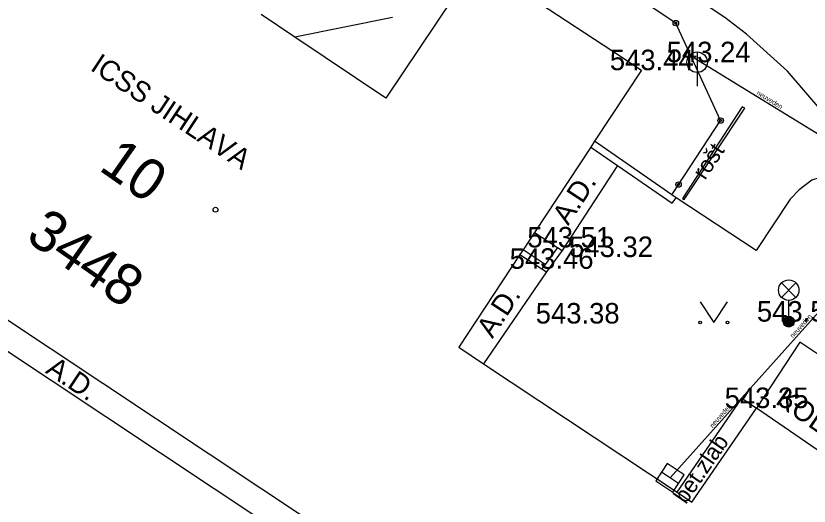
# Model space of a CAD drawing. Extents: x -669393 to -668650, y -1126925 to -1126294.
# Drawn here: x -668905.4 to -668876.38, y -1126626.61 to -1126608.7 of the extents above; entities that cross this region are included whole.
import ezdxf

# ---------------------------------------------------------------- set-up
doc = ezdxf.new("R2010")
doc.units = 0
for name, color, linetype in [('G_Bod_tecka', 7, 'Continuous'), ('G_Bod_vyska', 7, 'Continuous'), ('G_Budovy-znacky', 7, 'Continuous'), ('G_Budovy_Objekty', 7, 'Continuous'), ('G_Budovy_vstupy', 7, 'Continuous'), ('G_Cesty_Schody', 7, 'Continuous'), ('G_Cisla_orientacni', 7, 'Continuous'), ('G_Cisla_popisna', 7, 'Continuous'), ('G_Objekty_technicke', 7, 'Continuous'), ('G_Plochy_zpevnene', 7, 'Continuous'), ('G_Ploty', 7, 'Continuous'), ('G_Popisy_objektu', 7, 'Continuous'), ('G_Popisy_povrchu', 7, 'Continuous'), ('G_Poznamky_odkaz', 7, 'Continuous'), ('G_Site-kanalizace', 7, 'Continuous'), ('G_Site-Sloupy', 7, 'Continuous'), ('G_Z_KANAL_podz_kotovane', 7, 'Continuous'), ('G_Zelen-Znacky', 7, 'Continuous'), ('Vrstva 13', 7, 'Continuous'), ('Vrstva 3', 7, 'Continuous')]:
    doc.layers.add(name, color=color, linetype=linetype)

msp = doc.modelspace()

# ---------------------------------------------------------------- linework, layer by layer
at = {"layer": 'G_Bod_tecka'}
for p, q in [((-668880.43, -1126610.39), (-668880.43, -1126610.39)), ((-668882.51, -1126610.68), (-668882.51, -1126610.68)), ((-668885.59, -1126617.16), (-668885.59, -1126617.16)), ((-668884, -1126617.51), (-668884, -1126617.51)), ((-668886.16, -1126617.94), (-668886.16, -1126617.94)), ((-668885.22, -1126619.94), (-668885.22, -1126619.94)), ((-668877.13, -1126619.87), (-668877.13, -1126619.87)), ((-668878.31, -1126623.03), (-668878.31, -1126623.03))]:
    msp.add_line(p, q, dxfattribs=at)
at = {"layer": 'G_Budovy-znacky'}
msp.add_circle((-668898.099, -1126615.78), 0.0875, dxfattribs=at)
at = {"layer": 'G_Budovy_Objekty'}
for p, q in [((-668888.53, -1126606.7), (-668891.87, -1126611.7)), ((-668895.19, -1126609.47), (-668896.43, -1126608.64)), ((-668891.87, -1126611.7), (-668895.19, -1126609.47)), ((-668883.56, -1126609.99), (-668882.51, -1126610.68)), ((-668884.37, -1126613.49), (-668886.43, -1126616.61)), ((-668913.94, -1126614.34), (-668894.48, -1126627.26)), ((-668886.43, -1126616.61), (-668886.85, -1126617.25)), ((-668886.85, -1126617.25), (-668886.96, -1126617.42)), ((-668886.96, -1126617.42), (-668889.2, -1126620.81)), ((-668889.2, -1126620.81), (-668888.3, -1126621.41)), ((-668876.72, -1126620.62), (-668878.31, -1126623.03)), ((-668888.3, -1126621.41), (-668881.21, -1126626.11)), ((-668880.68, -1126626.47), (-668878.31, -1126623.03)), ((-668874.51, -1126625.65), (-668878.31, -1126623.03)), ((-668881.21, -1126626.11), (-668880.68, -1126626.47))]:
    msp.add_line(p, q, dxfattribs=at)
for points in [[(-668881.41, -1126615.23), (-668879.62, -1126612.52), (-668881.26, -1126608.96), (-668884.32, -1126606.92), (-668887.36, -1126604.92), (-668888.53, -1126606.7)], [(-668886.39, -1126608.12), (-668886.28, -1126608.2), (-668883.56, -1126609.99)], [(-668882.51, -1126610.68), (-668884.23, -1126613.28), (-668884.37, -1126613.49)]]:
    msp.add_lwpolyline(points, dxfattribs=at)
at = {"layer": 'G_Budovy_vstupy'}
msp.add_line((-668875.37, -1126621.53), (-668876.72, -1126620.62), dxfattribs=at)
at = {"layer": 'G_Cesty_Schody'}
for p, q in [((-668883.39, -1126614.16), (-668885.42, -1126617.27)), ((-668914.47, -1126615.14), (-668895, -1126628.05)), ((-668885.59, -1126617.16), (-668885.42, -1126617.27)), ((-668886.16, -1126617.94), (-668885.99, -1126618.05)), ((-668885.99, -1126618.05), (-668888.3, -1126621.41))]:
    msp.add_line(p, q, dxfattribs=at)
for points in [[(-668879.47, -1126608.75), (-668887.91, -1126603.16)], [(-668874.12, -1126614.81), (-668875.91, -1126612.19), (-668877.17, -1126610.71), (-668878.68, -1126609.36), (-668879.47, -1126608.75)], [(-668880.96, -1126615.41), (-668878.74, -1126612.07), (-668878.83, -1126612.02), (-668881.02, -1126615.37), (-668880.96, -1126615.41)]]:
    msp.add_lwpolyline(points, dxfattribs=at)
at = {"layer": 'G_Objekty_technicke'}
for p, q in [((-668877.395, -1126618.455), (-668876.865, -1126618.985)), ((-668877.395, -1126618.985), (-668876.865, -1126618.455)), ((-668877.13, -1126619.87), (-668877.13, -1126619.095))]:
    msp.add_line(p, q, dxfattribs=at)
for centre, radius in [((-668877.13, -1126618.72), 0.375), ((-668877.13, -1126619.87), 0.2), ((-668877.13, -1126619.87), 0.18), ((-668877.13, -1126619.87), 0.16), ((-668877.13, -1126619.87), 0.14), ((-668877.13, -1126619.87), 0.12), ((-668877.13, -1126619.87), 0.1), ((-668877.13, -1126619.87), 0.08), ((-668877.13, -1126619.87), 0.06), ((-668877.13, -1126619.87), 0.04), ((-668877.13, -1126619.87), 0.02)]:
    msp.add_circle(centre, radius, dxfattribs=at)
at = {"layer": 'G_Plochy_zpevnene'}
for p, q in [((-668891.62, -1126608.75), (-668895.19, -1126609.47)), ((-668881.21, -1126626.11), (-668878.84, -1126622.67)), ((-668878.84, -1126622.67), (-668878.31, -1126623.03))]:
    msp.add_line(p, q, dxfattribs=at)
for points in [[(-668881.39, -1126615.54), (-668881.25, -1126615.34), (-668881.41, -1126615.23), (-668884.23, -1126613.28)], [(-668884.37, -1126613.49), (-668883.39, -1126614.16), (-668881.39, -1126615.54)], [(-668874.12, -1126614.81), (-668875.03, -1126614.54), (-668875.67, -1126614.5), (-668876.28, -1126614.7), (-668876.75, -1126615.05), (-668877.08, -1126615.39), (-668878.32, -1126617.27), (-668881.25, -1126615.34)]]:
    msp.add_lwpolyline(points, dxfattribs=at)
at = {"layer": 'G_Ploty'}
for p, q in [((-668886.43, -1126616.61), (-668885.59, -1126617.16)), ((-668886.04, -1126617.78), (-668886.85, -1126617.25)), ((-668885.59, -1126617.16), (-668886.04, -1126617.78)), ((-668885.42, -1126617.27), (-668885.99, -1126618.05)), ((-668886.96, -1126617.42), (-668886.16, -1126617.94)), ((-668886.04, -1126617.78), (-668886.16, -1126617.94))]:
    msp.add_line(p, q, dxfattribs=at)
at = {"layer": 'G_Site-kanalizace'}
for p, q in [((-668880.48, -1126610.015), (-668880.48, -1126611.265)), ((-668881.158, -1126625.787), (-668881.782, -1126625.373))]:
    msp.add_line(p, q, dxfattribs=at)
msp.add_lwpolyline([(-668880.951, -1126625.476), (-668881.576, -1126625.061), (-668881.99, -1126625.686), (-668881.366, -1126626.101)], close=True, dxfattribs=at)
msp.add_circle((-668880.48, -1126610.39), 0.375, dxfattribs=at)
at = {"layer": 'G_Site-Sloupy'}
for centre, radius in [((-668881.26, -1126608.96), 0.1), ((-668881.26, -1126608.96), 0.0348), ((-668879.62, -1126612.52), 0.1), ((-668879.62, -1126612.52), 0.0348), ((-668881.16, -1126614.86), 0.1), ((-668881.16, -1126614.86), 0.0348)]:
    msp.add_circle(centre, radius, dxfattribs=at)
at = {"layer": 'G_Z_KANAL_podz_kotovane'}
msp.add_line((-668881.47, -1126625.58), (-668872.28, -1126615.32), dxfattribs=at)
msp.add_lwpolyline([(-668880.59, -1126610.23), (-668872.28, -1126615.32), (-668871.62, -1126615.73), (-668868.66, -1126624), (-668868.9, -1126631.81)], dxfattribs=at)
at = {"layer": 'G_Zelen-Znacky'}
for p, q in [((-668880.37, -1126619.15), (-668879.87, -1126619.9)), ((-668879.87, -1126619.9), (-668879.37, -1126619.15))]:
    msp.add_line(p, q, dxfattribs=at)
for centre in [(-668880.37, -1126619.9), (-668879.37, -1126619.9)]:
    msp.add_circle(centre, 0.05, dxfattribs=at)
at = {"layer": 'Vrstva 13'}
msp.add_line((-668881.472, -1126625.583), (-668872.283, -1126615.323), dxfattribs=at)
msp.add_lwpolyline([(-668880.587, -1126610.228), (-668872.283, -1126615.323), (-668871.62, -1126615.73), (-668868.66, -1126624), (-668868.9, -1126631.81)], dxfattribs=at)

# ---------------------------------------------------------------- texts
at = {"layer": 'G_Bod_vyska'}
for s, p in [('543.24', (-668881.594, -1126610.39)), ('543.44', (-668883.674, -1126610.68)), ('543.51', (-668886.692, -1126617.16)), ('543.32', (-668885.164, -1126617.51)), ('543.46', (-668887.338, -1126617.94)), ('543.54', (-668878.294, -1126619.87)), ('543.38', (-668886.384, -1126619.94)), ('543.35', (-668879.474, -1126623.03))]:
    msp.add_text(s, height=0.75, dxfattribs=at).set_placement(p)
at = {"layer": 'G_Cisla_orientacni'}
msp.add_text('10', height=1.5, rotation=325.1237, dxfattribs=at).set_placement((-668902.409, -1126614.306))
at = {"layer": 'G_Cisla_popisna'}
msp.add_text('3448', height=1.5, rotation=325.1237, dxfattribs=at).set_placement((-668905.089, -1126616.87))
at = {"layer": 'G_Popisy_objektu'}
msp.add_text('KOLNA', height=0.75, rotation=325.4148, dxfattribs=at).set_placement((-668877.656, -1126622.846))
at = {"layer": 'G_Popisy_povrchu'}
for s, rotation, p in [('rošt', 56.4684, (-668880.191, -1126614.723)), ('bet.zlab', 55.4295, (-668880.894, -1126626.572))]:
    msp.add_text(s, height=0.6, rotation=rotation, dxfattribs=at).set_placement(p)
at = {"layer": 'G_Poznamky_odkaz'}
for s, rotation, p in [('ICSS JIHLAVA', 326.495, (-668902.714, -1126610.655)), ('A.D.', 56.8285, (-668885.198, -1126616.384)), ('A.D.', 56.8285, (-668887.968, -1126620.514)), ('A.D.', 326.4528, (-668904.35, -1126621.726))]:
    msp.add_text(s, height=0.75, rotation=rotation, dxfattribs=at).set_placement(p)
at = {"layer": 'Vrstva 3'}
for rotation, p in [(328.4289, (-668878.323, -1126611.555)), (48.1281, (-668876.975, -1126620.484)), (48.15, (-668879.916, -1126623.767))]:
    msp.add_text('neuveden', height=0.1755, rotation=rotation, dxfattribs=at).set_placement(p)

doc.saveas('drawing.dxf')
